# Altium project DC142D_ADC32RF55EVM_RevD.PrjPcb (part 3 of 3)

## Sheet DC142D_ADC32RF55_FMC_RevA1.SchDoc: FMC Connector
size 431 x 279 mm; Date: Not shown in title block; ApprovedBy: Not shown in title block; CheckedBy: Not shown in title block; Author: Not shown in title block; CompanyName: Not shown in title block; DrawnBy: CW; Engineer: Not shown in title block; Organization: Not shown in title block; Address1: Not shown in title block; Address2: Not shown in title block; Address3: Not shown in title block; Address4: Not shown in title block; DocumentNumber: 5; Revision: Use project parameter SCH_Rev; SheetNumber: 11; SheetTotal: 13; PageSetup: Record=PageOptions¦CenterHorizontal=True¦CenterVertical=True¦PrintScale=1.00¦XCorrection=1.00¦YCorrection=1.00¦PrintKind=0¦BorderSize=5000000¦LeftOffset=0¦BottomOffset=0¦Orientation=2¦PaperLength=1000¦PaperWidth=1000¦Scale=100¦PaperSource=15¦PrintQuality=600¦MediaType=1¦DitherType=10¦PaperKind=Letter¦PrintScaleMode=1
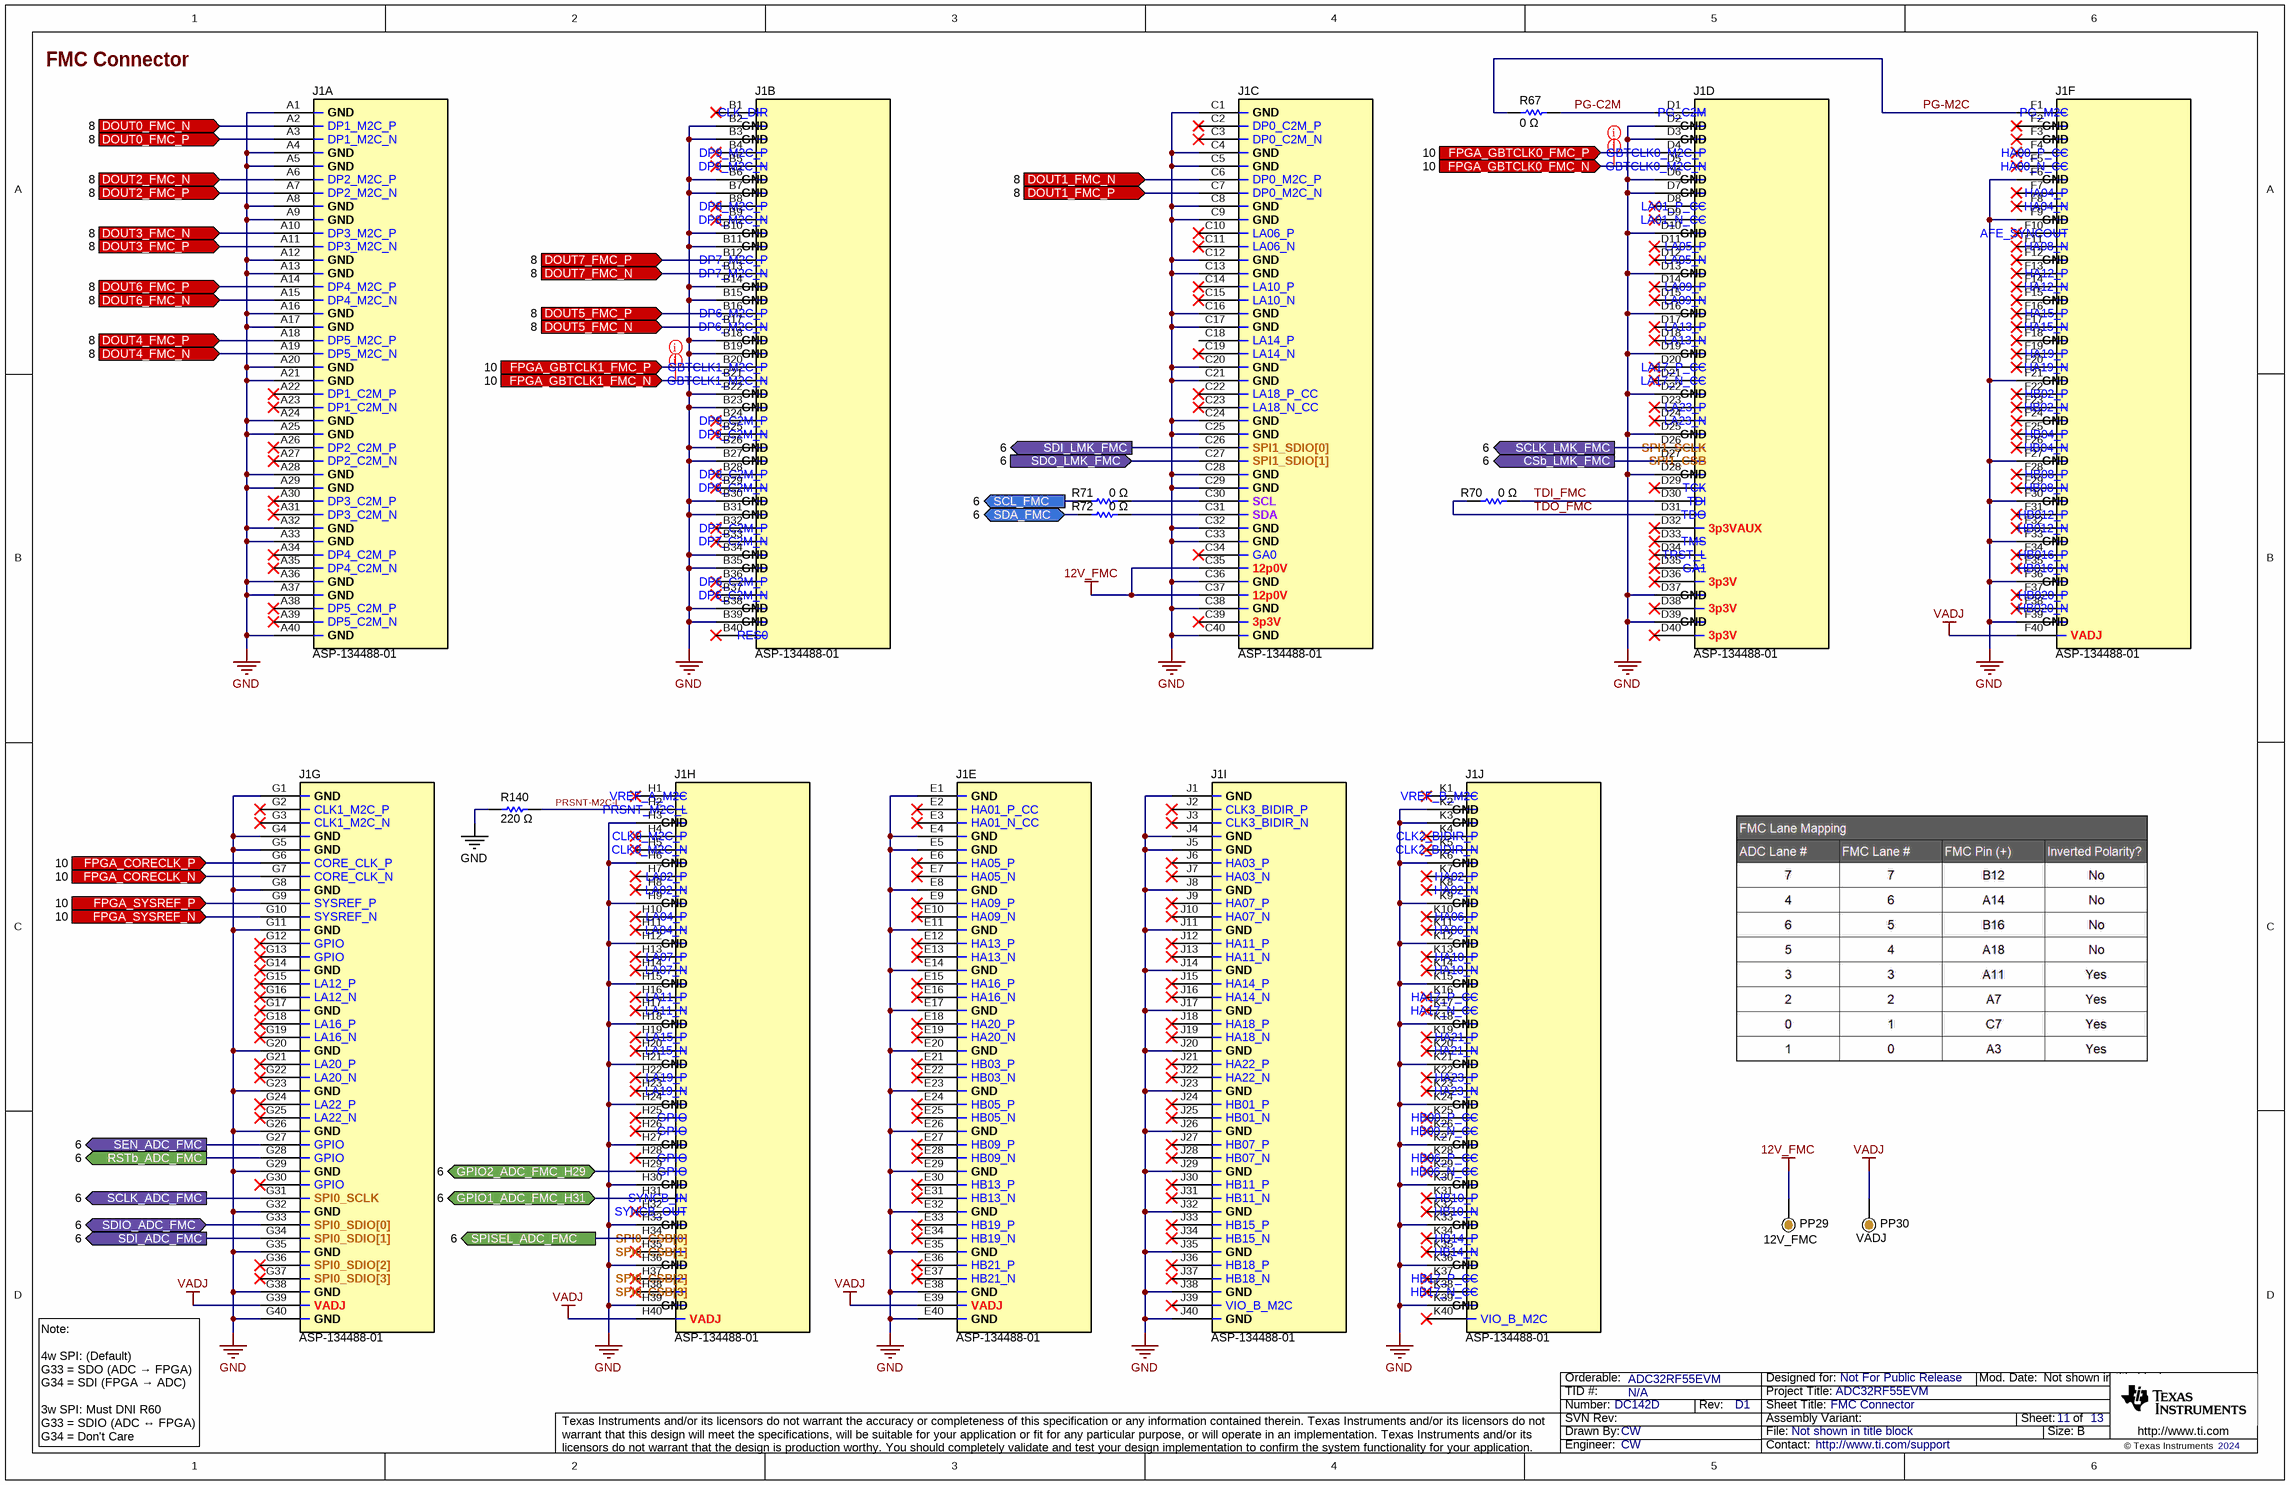
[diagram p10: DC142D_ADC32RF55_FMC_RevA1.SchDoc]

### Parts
J1  ASP-134488-01  [SAMTEC_ASP-134488-01]  (parts A,B,C,D,E,F,G,H,I,J of 10)
PP29  Text1: 12V_FMC  [ProbePoint_TH_40mil]  (hidden comment: Probe Point)  (no BOM)
PP30  Text1: VADJ  [ProbePoint_TH_40mil]  (hidden comment: Probe Point)  (no BOM)
R67  value 0 Ω  [0201]  (hidden comment: ERJ-1GN0R00C)
R70  value 0 Ω  [0201]  (hidden comment: ERJ-1GN0R00C)
R71  value 0 Ω  [0201]  (hidden comment: ERJ-1GN0R00C)
R72  value 0 Ω  [0201]  (hidden comment: ERJ-1GN0R00C)
R140  value 220 Ω  [0201]  (hidden comment: ERJ-1GNF2200C)

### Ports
CSb_LMK_FMC (out, see 6), DOUT0_FMC_N (in, see 8), DOUT0_FMC_P (in, see 8), DOUT1_FMC_N (in, see 8), DOUT1_FMC_P (in, see 8), DOUT2_FMC_N (in, see 8), DOUT2_FMC_P (in, see 8), DOUT3_FMC_N (in, see 8), DOUT3_FMC_P (in, see 8), DOUT4_FMC_N (in, see 8), DOUT4_FMC_P (in, see 8), DOUT5_FMC_N (in, see 8), DOUT5_FMC_P (in, see 8), DOUT6_FMC_N (in, see 8), DOUT6_FMC_P (in, see 8), DOUT7_FMC_N (in, see 8), DOUT7_FMC_P (in, see 8), FPGA_CORECLK_N (in, see 10), FPGA_CORECLK_P (in, see 10), FPGA_GBTCLK0_FMC_N (in, see 10), FPGA_GBTCLK0_FMC_P (in, see 10), FPGA_GBTCLK1_FMC_N (in, see 10), FPGA_GBTCLK1_FMC_P (in, see 10), FPGA_SYSREF_N (in, see 10), FPGA_SYSREF_P (in, see 10), GPIO1_ADC_FMC_H31 (bidir, see 6), GPIO2_ADC_FMC_H29 (bidir, see 6), RSTb_ADC_FMC (out, see 6), SCL_FMC (out, see 6), SCLK_ADC_FMC (out, see 6), SCLK_LMK_FMC (out, see 6), SDA_FMC (bidir, see 6), SDI_ADC_FMC (out, see 6), SDI_LMK_FMC (out, see 6), SDIO_ADC_FMC (bidir, see 6), SDO_LMK_FMC (in, see 6), SEN_ADC_FMC (out, see 6), SPISEL_ADC_FMC (out, see 6)

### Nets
12V_FMC: J1.C35 J1.C37 PP29.1
GND: J1.A1 J1.A4 J1.A5 J1.A8 J1.A9 J1.A12 J1.A13 J1.A16 J1.A17 J1.A20 J1.A21 J1.A24 J1.A25 J1.A28 J1.A29 J1.A32 J1.A33 J1.A36 J1.A37 J1.A40 J1.B2 J1.B3 J1.B6 J1.B7 J1.B10 J1.B11 J1.B14 J1.B15 J1.B18 J1.B19 J1.B22 J1.B23 J1.B26 J1.B27 J1.B30 J1.B31 J1.B34 J1.B35 J1.B38 J1.B39 J1.C1 J1.C4 J1.C5 J1.C8 J1.C9 J1.C12 J1.C13 J1.C16 J1.C17 J1.C20 J1.C21 J1.C24 J1.C25 J1.C28 J1.C29 J1.C32 J1.C33 J1.C36 J1.C38 J1.C40 J1.D2 J1.D3 J1.D6 J1.D7 J1.D10 J1.D13 J1.D16 J1.D19 J1.D22 J1.D25 J1.D28 J1.D37 J1.D39 J1.E1 J1.E4 J1.E5 J1.E8 J1.E11 J1.E14 J1.E17 J1.E20 J1.E23 J1.E26 J1.E29 J1.E32 J1.E35 J1.E38 J1.E40 J1.F6 J1.F9 J1.F21 J1.F27 J1.F30 J1.F33 J1.F36 J1.F39 J1.G1 J1.G4 J1.G5 J1.G8 J1.G11 J1.G20 J1.G23 J1.G26 J1.G29 J1.G32 J1.G35 J1.G38 J1.G40 J1.H3 J1.H6 J1.H9 J1.H12 J1.H15 J1.H18 J1.H21 J1.H24 J1.H27 J1.H30 J1.H33 J1.H36 J1.H39 J1.J1 J1.J4 J1.J5 J1.J8 J1.J11 J1.J14 J1.J17 J1.J20 J1.J23 J1.J26 J1.J29 J1.J32 J1.J35 J1.J38 J1.J40 J1.K2 J1.K3 J1.K6 J1.K9 J1.K12 J1.K15 J1.K18 J1.K21 J1.K24 J1.K27 J1.K30 J1.K33 J1.K36 J1.K39 R140.1
VADJ: J1.E39 J1.F40 J1.G39 J1.H40 PP30.1
CSb_LMK_FMC: J1.D27 ; port CSb_LMK_FMC
DOUT0_FMC_N: J1.A2 ; port DOUT0_FMC_N
DOUT0_FMC_P: J1.A3 ; port DOUT0_FMC_P
DOUT1_FMC_N: J1.C6 ; port DOUT1_FMC_N
DOUT1_FMC_P: J1.C7 ; port DOUT1_FMC_P
DOUT2_FMC_N: J1.A6 ; port DOUT2_FMC_N
DOUT2_FMC_P: J1.A7 ; port DOUT2_FMC_P
DOUT3_FMC_N: J1.A10 ; port DOUT3_FMC_N
DOUT3_FMC_P: J1.A11 ; port DOUT3_FMC_P
DOUT4_FMC_N: J1.A19 ; port DOUT4_FMC_N
DOUT4_FMC_P: J1.A18 ; port DOUT4_FMC_P
DOUT5_FMC_N: J1.B17 ; port DOUT5_FMC_N
DOUT5_FMC_P: J1.B16 ; port DOUT5_FMC_P
DOUT6_FMC_N: J1.A15 ; port DOUT6_FMC_N
DOUT6_FMC_P: J1.A14 ; port DOUT6_FMC_P
DOUT7_FMC_N: J1.B13 ; port DOUT7_FMC_N
DOUT7_FMC_P: J1.B12 ; port DOUT7_FMC_P
FPGA_CORECLK_N: J1.G7 ; port FPGA_CORECLK_N
FPGA_CORECLK_P: J1.G6 ; port FPGA_CORECLK_P
FPGA_GBTCLK0_FMC_N: J1.D5 ; port FPGA_GBTCLK0_FMC_N
FPGA_GBTCLK0_FMC_P: J1.D4 ; port FPGA_GBTCLK0_FMC_P
FPGA_GBTCLK1_FMC_N: J1.B21 ; port FPGA_GBTCLK1_FMC_N
FPGA_GBTCLK1_FMC_P: J1.B20 ; port FPGA_GBTCLK1_FMC_P
FPGA_SYSREF_N: J1.G10 ; port FPGA_SYSREF_N
FPGA_SYSREF_P: J1.G9 ; port FPGA_SYSREF_P
GPIO1_ADC_FMC_H31: J1.H31 ; port GPIO1_ADC_FMC_H31
GPIO2_ADC_FMC_H29: J1.H29 ; port GPIO2_ADC_FMC_H29
PG-C2M: J1.D1 R67.2
PG-M2C: J1.F1 R67.1
PRSNT-M2C-L: J1.H2 R140.2
RSTb_ADC_FMC: J1.G28 ; port RSTb_ADC_FMC
SCL_FMC: R71.2 ; port SCL_FMC
SCLK_ADC_FMC: J1.G31 ; port SCLK_ADC_FMC
SCLK_LMK_FMC: J1.D26 ; port SCLK_LMK_FMC
SDA_FMC: R72.2 ; port SDA_FMC
SDI_ADC_FMC: J1.G34 ; port SDI_ADC_FMC
SDI_LMK_FMC: J1.C26 ; port SDI_LMK_FMC
SDIO_ADC_FMC: J1.G33 ; port SDIO_ADC_FMC
SDO_LMK_FMC: J1.C27 ; port SDO_LMK_FMC
SEN_ADC_FMC: J1.G27 ; port SEN_ADC_FMC
SPISEL_ADC_FMC: J1.H34 ; port SPISEL_ADC_FMC
TDI_FMC: J1.D30 R70.1
TDO_FMC: J1.D31 R70.2
NetJ1_C30: J1.C30 R71.1
NetJ1_C31: J1.C31 R72.1

Not connected (* = marked no-connect by the designer): J1 A22* A23* A26* A27* A30* A31* A34* A35* A38* A39* B1* B4* B5* B8* B9* B24* B25* B28* B29* B32* B33* B36* B37* B40* C2* C3* C10* C11* C14* C15* C18 C19* C22* C23* C34* C39* D8* D9* D11* D12* D14* D15* D17* D18* D20* D21* D23* D24* D29* D32* D33* D34* D35* D36* D38* D40* E2* E3* E6* E7* E9* E10* E12* E13* E15* E16* E18* E19* E21* E22* E24* E25* E27* E28* E30* E31* E33* E34* E36* E37* F2* F3* F4* F5* F7* F8* F10* F11* F12* F13* F14* F15* F16* F17* F18* F19* F20* F22* F23* F24* F25* F26* F28* F29* F31* F32* F34* F35* F37* F38* G2* G3* G12* G13* G14* G15* G16* G17* G18* G19* G21* G22* G24* G25* G30* G36* G37* H1* H4* H5* H7* H8* H10* H11* H13* H14* H16* H17* H19* H20* H22* H23* H25* H26* H28* H32* H35* H37* H38* J2* J3* J6* J7* J9* J10* J12* J13* J15* J16* J18* J19* J21* J22* J24* J25* J27* J28* J30* J31* J33* J34* J36* J37* J39* K1* K4* K5* K7* K8* K10* K11* K13* K14* K16* K17* K19* K20* K22* K23* K25* K26* K28* K29* K31* K32* K34* K35* K37* K38* K40*

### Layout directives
net class GBT CLK: FPGA_GBTCLK0_FMC_N, FPGA_GBTCLK0_FMC_P, FPGA_GBTCLK1_FMC_N, FPGA_GBTCLK1_FMC_P

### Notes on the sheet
- Note:
  4w SPI: (Default)
  G33 = SDO (ADC → FPGA)
  G34 = SDI (FPGA → ADC)
  3w SPI: Must DNI R60
  G33 = SDIO (ADC ↔ FPGA)
  G34 = Don't Care

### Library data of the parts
J1 = ASP-134488-01: FMC, High Density Array, Male / EVM Connector 40x10; Manufacturer: Samtec; UniqueID: cmp00010; Pitch (mm): 1.27
PP29 PP30 = cmp00025: Probe Point that can be used in lue of a test point
R67 R70-R72 = RSMD020101699: RES SMD 0 OHM JUMPER 1/20W 0201; Manufacturer: Panasonic Electronic Components; CompType: Resistor SMD; Power (Watts): 0.05W, 1/20W
R140 = RSMD020100147: RES SMD 220 OHM 1% 1/20W 0201; Manufacturer: Panasonic Electronic Components; CompType: Resistor SMD; Power (Watts): 0.05W, 1/20W; Temperature Coefficient: ±200ppm/°C

## Sheet DC142D_ADC32RF55_Misc_RevA1.SchDoc: Misc Hardware
size 431 x 279 mm; Date: Not shown in title block; ApprovedBy: Not shown in title block; CheckedBy: Not shown in title block; Author: Not shown in title block; CompanyName: Not shown in title block; DrawnBy: CW; Engineer: Not shown in title block; Organization: Not shown in title block; Address1: Not shown in title block; Address2: Not shown in title block; Address3: Not shown in title block; Address4: Not shown in title block; DocumentNumber: 12; Revision: Use project parameter SCH_Rev; SheetNumber: 12; SheetTotal: 13; PageSetup: Record=PageOptions¦CenterHorizontal=True¦CenterVertical=True¦PrintScale=1.00¦XCorrection=1.00¦YCorrection=1.00¦PrintKind=0¦BorderSize=5000000¦LeftOffset=0¦BottomOffset=0¦Orientation=2¦PaperLength=1000¦PaperWidth=1000¦Scale=100¦PaperSource=15¦PrintQuality=600¦MediaType=1¦DitherType=10¦PaperKind=Letter¦PrintScaleMode=1
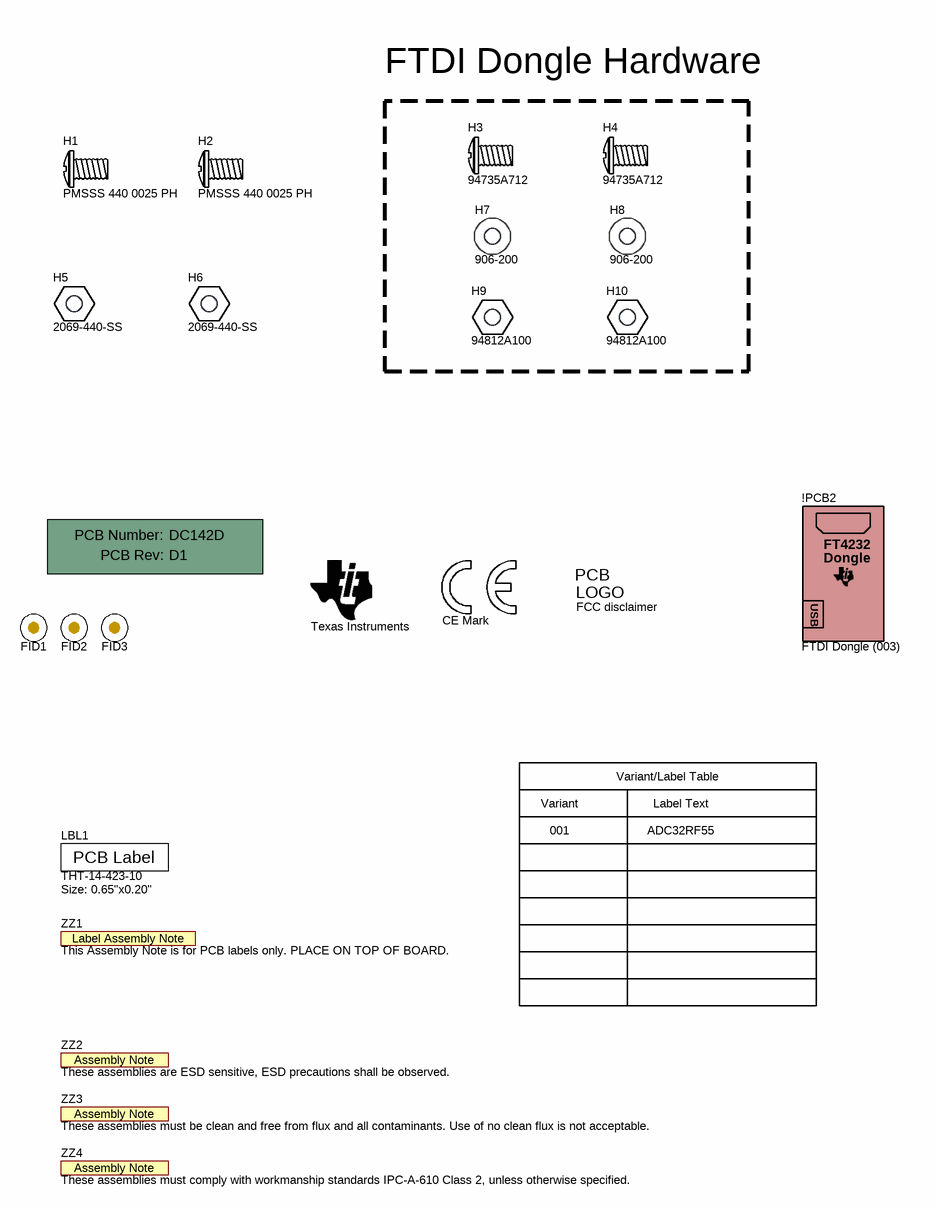
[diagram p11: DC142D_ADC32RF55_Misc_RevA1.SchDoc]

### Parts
!PCB  Printed Circuit Board  (value not drawn)  (mechanical)
!PCB2  FTDI Dongle (003)  (mechanical)
FID1  Fiducial Mark  [Fiducial10-20]  (value not drawn)  (no BOM)
FID2  Fiducial Mark  [Fiducial10-20]  (value not drawn)  (no BOM)
FID3  Fiducial Mark  [Fiducial10-20]  (value not drawn)  (no BOM)
H1  PMSSS 440 0025 PH  [4400025PH]  (mechanical)
H2  PMSSS 440 0025 PH  [4400025PH]  (mechanical)
H3  94735A712  [MCSNY 256 0025]  (mechanical)
H4  94735A712  [MCSNY 256 0025]  (mechanical)
H5  2069-440-SS  [FP-2116-440-AL_STANDOFF_HEX_1-4-MFG]
H6  2069-440-SS  [FP-2116-440-AL_STANDOFF_HEX_1-4-MFG]
H7  906-200  [Bivar_906-200]
H8  906-200  [Bivar_906-200]
H9  94812A100  [MMCNYN256]
H10  94812A100  [MMCNYN256]
LBL1  THT-14-423-10  Text1: Size: 0.65"x0.20"  [Label_650x200]
Logo1  Texas Instruments  [TI_Stacked_Overlay_Medium]  (no BOM)
LOGO2  CE Mark  [CE_Mark_5mm]  (no BOM)
Logo3  FCC disclaimer  [FCC_disclaimer]  (no BOM)
Logo4  WEEE  [WEEE_Minimum]  (value not drawn)  (no BOM)
ZZ1  This Assembly Note is for PCB labels only. PLACE ON TOP OF BOARD.  [AssemblyNoteLabel]  (no BOM)
ZZ2  These assemblies are ESD sensitive, ESD precautions shall be observed.  [AssemblyNote]  (no BOM)
ZZ3  These assemblies must be clean and free from flux and all contaminants. Use of no clean flux is not acceptable.  [AssemblyNote]  (no BOM)
ZZ4  These assemblies must comply with workmanship standards IPC-A-610 Class 2, unless otherwise specified.  [AssemblyNote]  (no BOM)

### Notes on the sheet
- FTDI Dongle Hardware
- Variant/Label Table
- Variant
- 001
- Label Text
- ADC32RF55

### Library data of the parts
!PCB = cmp00109: CompType: PCB
!PCB2 = cmp00363: FTDI Dongle RevA Variant 003; Manufacturer: Texas Instruments; CompType: Peripheral Board
FID1-FID3 = cmp00099: Fiducial; SymbolCreator: a0412235
H1 H2 = cmp00095: MACHINE SCREW PAN PHILLIPS 4-40; Manufacturer: B&F Fastener Supply
H3 H4 = cmp00392: Nylon Pan Head Screws Phillips, 2-56 Thread, 1/2" Long; Manufacturer: McMaster-Carr; CompType: Machine Screw
H5 H6 = cmp00097: Hex Standoff Threaded #4-40 Stainless Steel 1.250" (31.75mm) 1 1/4; Manufacturer: RAF Electronic Hardware; Pitch (mm): 4-40
H7 H8 = cmp00357: Round Nylon Spacer 5.08mm; Manufacturer: Bivar Inc
H9 H10 = cmp00391: Hex Nut 3/16" Nylon 2-56; Manufacturer: McMaster-Carr; CompType: Hex Nut
LBL1 = cmp00106: Thermal Transfer Printable Labels, 0.650" W x 0.200" H - 10,000 per roll; Manufacturer: Brady; CompType: Label
Logo1 = cmp00104: Texas Instrument Corporate Signature; PartNumber: TI Bug; CompType: Logo
LOGO2 = cmp00103: CE_Mark; CompType: Logo
Logo3 = CMP-0074847-1: FCC_disclaimer; Library Reference: Logo
Logo4 = cmp00101: CompType: Logo
ZZ1 = cmp00107: This Assembly Note is for PCB labels only; SymbolCreator: a0412235
ZZ2 = CMP-0077236-1
ZZ3 = CMP-0077237-1
ZZ4 = CMP-0077238-1

## Sheet DC142D_ADC32RF55_Revision History.SchDoc: Rev History & Variants
size 431 x 279 mm; Date: Not shown in title block; ApprovedBy: Not shown in title block; CheckedBy: Not shown in title block; Author: Not shown in title block; CompanyName: Not shown in title block; DrawnBy: CW; Engineer: Not shown in title block; Organization: Not shown in title block; Address1: Not shown in title block; Address2: Not shown in title block; Address3: Not shown in title block; Address4: Not shown in title block; DocumentNumber: 13; Revision: Use project parameter SCH_Rev; SheetNumber: 13; SheetTotal: 13; PageSetup: Record=PageOptions¦CenterHorizontal=True¦CenterVertical=True¦PrintScale=1.00¦XCorrection=1.00¦YCorrection=1.00¦PrintKind=0¦BorderSize=5000000¦LeftOffset=0¦BottomOffset=0¦Orientation=2¦PaperLength=1000¦PaperWidth=1000¦Scale=100¦PaperSource=15¦PrintQuality=600¦MediaType=1¦DitherType=10¦PaperKind=Letter¦PrintScaleMode=1
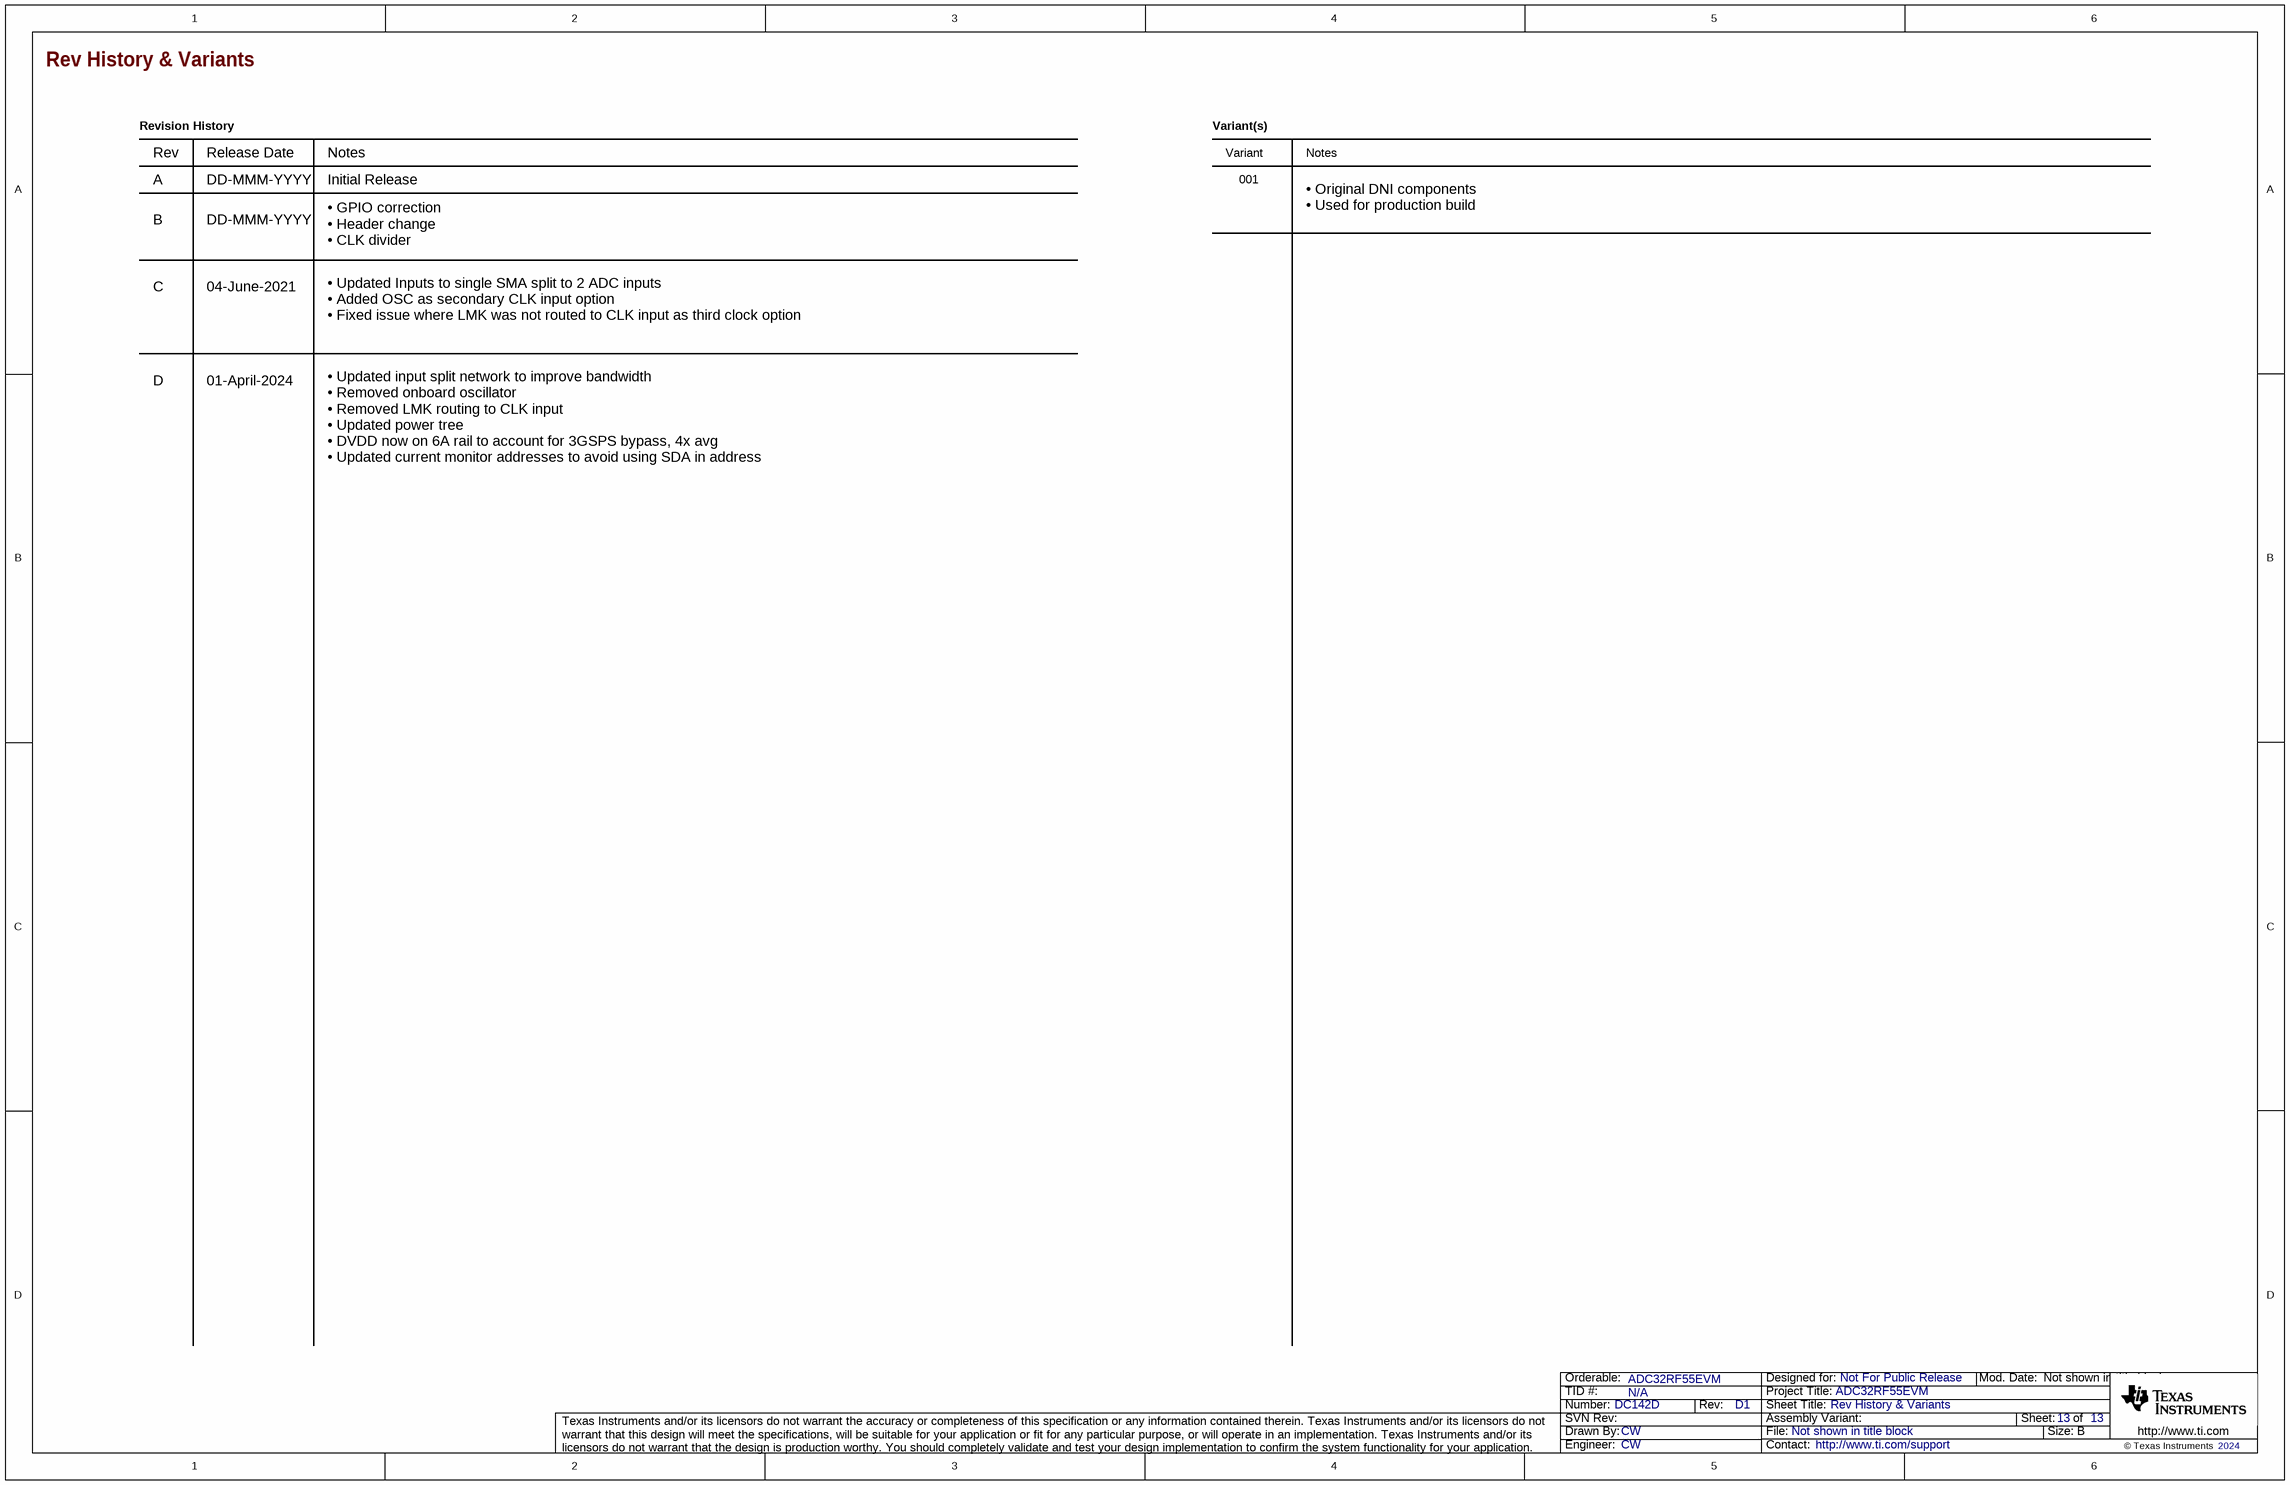
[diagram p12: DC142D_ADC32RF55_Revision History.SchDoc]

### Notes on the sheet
- Revision History
- Rev
- Release Date
- Notes
- Variant(s)
- Variant
- A
- B
- DD-MMM-YYYY
- Initial Release
- 001
- C
- 04-June-2021
- • GPIO correction
  • Header change
  • CLK divider
- • Original DNI components
  • Used for production build
- • Updated Inputs to single SMA split to 2 ADC inputs
  • Added OSC as secondary CLK input option
  • Fixed issue where LMK was not routed to CLK input as third clock option
- D
- 01-April-2024
- • Updated input split network to improve bandwidth
  • Removed onboard oscillator
  • Removed LMK routing to CLK input
  • Updated power tree
  • DVDD now on 6A rail to account for 3GSPS bypass, 4x avg
  • Updated current monitor addresses to avoid using SDA in address

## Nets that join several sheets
3p3V_Utility: DC142D_ADC32RF55_Power1_RevA1 (5 pins), DC142D_ADC32RF55_Power2_RevA1 (9 pins), DC142D_ADC32RF55_Power3_RevA1 (9 pins), DC142D_ADC32RF55_USB_RevA1 (19 pins), DC142D_ADC32RF55_MUX_RevA1 (12 pins), DC142D_ADC32RF55_ADC_Power_RevA1 (C132.2 U29.B1 U29.C1), DC142D_ADC32RF55_LMK_RevA1 (26 pins)
12V: DC142D_ADC32RF55_Power1_RevA1 (9 pins), DC142D_ADC32RF55_Power2_RevA1 (C19.2 C20.2 R11.1 U6.18), DC142D_ADC32RF55_Power3_RevA1 (11 pins)
12V_FMC: DC142D_ADC32RF55_Power1_RevA1 (SW1.1), DC142D_ADC32RF55_FMC_RevA1 (J1.C35 J1.C37 PP29.1)
AVDD12: DC142D_ADC32RF55_Power2_RevA1 (FC4.3 PP8.1), DC142D_ADC32RF55_ADC_Power_RevA1 (11 pins)
AVDD18: DC142D_ADC32RF55_Power3_RevA1 (FC6.3 PP12.1), DC142D_ADC32RF55_ADC_Dig_RevA1 (5 pins), DC142D_ADC32RF55_ADC_Power_RevA1 (11 pins)
CLKVDD: DC142D_ADC32RF55_Power2_RevA1 (FC3.3 PP6.1), DC142D_ADC32RF55_ADC_Power_RevA1 (C120.2 C121.2 U1.25)
DVDD: DC142D_ADC32RF55_Power3_RevA1 (6 pins), DC142D_ADC32RF55_ADC_Power_RevA1 (18 pins)
GND: DC142D_ADC32RF55_Power1_RevA1 (39 pins), DC142D_ADC32RF55_Power2_RevA1 (53 pins), DC142D_ADC32RF55_Power3_RevA1 (57 pins), DC142D_ADC32RF55_USB_RevA1 (40 pins), DC142D_ADC32RF55_MUX_RevA1 (25 pins), DC142D_ADC32RF55_ADC_Input_RevA1 (16 pins), DC142D_ADC32RF55_ADC_Dig_RevA1 (12 pins), DC142D_ADC32RF55_ADC_Power_RevA1 (36 pins), DC142D_ADC32RF55_LMK_RevA1 (25 pins), DC142D_ADC32RF55_FMC_RevA1 (152 pins)
VADJ: DC142D_ADC32RF55_MUX_RevA1 (7 pins), DC142D_ADC32RF55_FMC_RevA1 (5 pins)
VDDL18: DC142D_ADC32RF55_Power3_RevA1 (C65.2 PP13.1 U15.1), DC142D_ADC32RF55_USB_RevA1 (U21.13 U22.2 U22.5 U23.13), DC142D_ADC32RF55_MUX_RevA1 (R56.1 R57.1)
ADC_SYSREF_N: DC142D_ADC32RF55_ADC_Dig_RevA1 (R74.2 U1.28), DC142D_ADC32RF55_LMK_RevA1 (R146.1 R150.1)
ADC_SYSREF_P: DC142D_ADC32RF55_ADC_Dig_RevA1 (R74.1 U1.27), DC142D_ADC32RF55_LMK_RevA1 (R147.1 R149.1)
CLK_LMK: DC142D_ADC32RF55_ADC_Dig_RevA1 (R135.2), DC142D_ADC32RF55_LMK_RevA1 (C105.1)
CSb_LMK: DC142D_ADC32RF55_MUX_RevA1 (R46.2), DC142D_ADC32RF55_LMK_RevA1 (U2.18)
CSb_LMK_FMC: DC142D_ADC32RF55_MUX_RevA1 (R47.2 U17.2), DC142D_ADC32RF55_FMC_RevA1 (J1.D27)
CSb_LMK_USB: DC142D_ADC32RF55_USB_RevA1 (J3.29), DC142D_ADC32RF55_MUX_RevA1 (R40.2 U16.3)
DOUT0_FMC_N: DC142D_ADC32RF55_ADC_Dig_RevA1 (C85.2), DC142D_ADC32RF55_FMC_RevA1 (J1.A2)
DOUT0_FMC_P: DC142D_ADC32RF55_ADC_Dig_RevA1 (C84.2), DC142D_ADC32RF55_FMC_RevA1 (J1.A3)
DOUT1_FMC_N: DC142D_ADC32RF55_ADC_Dig_RevA1 (C87.2), DC142D_ADC32RF55_FMC_RevA1 (J1.C6)
DOUT1_FMC_P: DC142D_ADC32RF55_ADC_Dig_RevA1 (C86.2), DC142D_ADC32RF55_FMC_RevA1 (J1.C7)
DOUT2_FMC_N: DC142D_ADC32RF55_ADC_Dig_RevA1 (C89.2), DC142D_ADC32RF55_FMC_RevA1 (J1.A6)
DOUT2_FMC_P: DC142D_ADC32RF55_ADC_Dig_RevA1 (C88.2), DC142D_ADC32RF55_FMC_RevA1 (J1.A7)
DOUT3_FMC_N: DC142D_ADC32RF55_ADC_Dig_RevA1 (C93.2), DC142D_ADC32RF55_FMC_RevA1 (J1.A10)
DOUT3_FMC_P: DC142D_ADC32RF55_ADC_Dig_RevA1 (C90.2), DC142D_ADC32RF55_FMC_RevA1 (J1.A11)
DOUT4_FMC_N: DC142D_ADC32RF55_ADC_Dig_RevA1 (C95.2), DC142D_ADC32RF55_FMC_RevA1 (J1.A19)
DOUT4_FMC_P: DC142D_ADC32RF55_ADC_Dig_RevA1 (C94.2), DC142D_ADC32RF55_FMC_RevA1 (J1.A18)
DOUT5_FMC_N: DC142D_ADC32RF55_ADC_Dig_RevA1 (C97.2), DC142D_ADC32RF55_FMC_RevA1 (J1.B17)
DOUT5_FMC_P: DC142D_ADC32RF55_ADC_Dig_RevA1 (C96.2), DC142D_ADC32RF55_FMC_RevA1 (J1.B16)
DOUT6_FMC_N: DC142D_ADC32RF55_ADC_Dig_RevA1 (C100.2), DC142D_ADC32RF55_FMC_RevA1 (J1.A15)
DOUT6_FMC_P: DC142D_ADC32RF55_ADC_Dig_RevA1 (C98.2), DC142D_ADC32RF55_FMC_RevA1 (J1.A14)
DOUT7_FMC_N: DC142D_ADC32RF55_ADC_Dig_RevA1 (C104.2), DC142D_ADC32RF55_FMC_RevA1 (J1.B13)
DOUT7_FMC_P: DC142D_ADC32RF55_ADC_Dig_RevA1 (C102.2), DC142D_ADC32RF55_FMC_RevA1 (J1.B12)
FPGA_CORECLK_N: DC142D_ADC32RF55_LMK_RevA1 (C138.2), DC142D_ADC32RF55_FMC_RevA1 (J1.G7)
FPGA_CORECLK_P: DC142D_ADC32RF55_LMK_RevA1 (C137.2), DC142D_ADC32RF55_FMC_RevA1 (J1.G6)
FPGA_GBTCLK0_FMC_N: DC142D_ADC32RF55_LMK_RevA1 (C136.2), DC142D_ADC32RF55_FMC_RevA1 (J1.D5)
FPGA_GBTCLK0_FMC_P: DC142D_ADC32RF55_LMK_RevA1 (C135.2), DC142D_ADC32RF55_FMC_RevA1 (J1.D4)
FPGA_GBTCLK1_FMC_N: DC142D_ADC32RF55_LMK_RevA1 (C134.2), DC142D_ADC32RF55_FMC_RevA1 (J1.B21)
FPGA_GBTCLK1_FMC_P: DC142D_ADC32RF55_LMK_RevA1 (C133.2), DC142D_ADC32RF55_FMC_RevA1 (J1.B20)
FPGA_SYSREF_N: DC142D_ADC32RF55_LMK_RevA1 (R157.1 R161.1), DC142D_ADC32RF55_FMC_RevA1 (J1.G10)
FPGA_SYSREF_P: DC142D_ADC32RF55_LMK_RevA1 (R158.1 R160.1), DC142D_ADC32RF55_FMC_RevA1 (J1.G9)
GPIO1_ADC: DC142D_ADC32RF55_MUX_RevA1 (PP23.1 U32.2), DC142D_ADC32RF55_ADC_Dig_RevA1 (U1.39)
GPIO1_ADC_FMC_H31: DC142D_ADC32RF55_MUX_RevA1 (U32.1), DC142D_ADC32RF55_FMC_RevA1 (J1.H31)
GPIO1_ADC_USB: DC142D_ADC32RF55_USB_RevA1 (U23.12), DC142D_ADC32RF55_MUX_RevA1 (U32.16)
GPIO2_ADC: DC142D_ADC32RF55_MUX_RevA1 (PP24.1 U32.5), DC142D_ADC32RF55_ADC_Dig_RevA1 (U1.38)
GPIO2_ADC_FMC_H29: DC142D_ADC32RF55_MUX_RevA1 (U32.4), DC142D_ADC32RF55_FMC_RevA1 (J1.H29)
GPIO2_ADC_USB: DC142D_ADC32RF55_USB_RevA1 (U23.11), DC142D_ADC32RF55_MUX_RevA1 (U32.3)
INA1_ADC_N: DC142D_ADC32RF55_ADC_Input_RevA1 (C68.2 R104.2), DC142D_ADC32RF55_ADC_Dig_RevA1 (U1.15)
INA1_ADC_P: DC142D_ADC32RF55_ADC_Input_RevA1 (C74.2 R104.1), DC142D_ADC32RF55_ADC_Dig_RevA1 (U1.14)
INA2_ADC_N: DC142D_ADC32RF55_ADC_Input_RevA1 (C78.2 R111.1), DC142D_ADC32RF55_ADC_Dig_RevA1 (U1.19)
INA2_ADC_P: DC142D_ADC32RF55_ADC_Input_RevA1 (C75.2 R111.2), DC142D_ADC32RF55_ADC_Dig_RevA1 (U1.18)
INB1_ADC_N: DC142D_ADC32RF55_ADC_Input_RevA1 (C155.2 R126.2), DC142D_ADC32RF55_ADC_Dig_RevA1 (U1.34)
INB1_ADC_P: DC142D_ADC32RF55_ADC_Input_RevA1 (C158.2 R126.1), DC142D_ADC32RF55_ADC_Dig_RevA1 (U1.35)
INB2_ADC_N: DC142D_ADC32RF55_ADC_Input_RevA1 (C79.2 R119.2), DC142D_ADC32RF55_ADC_Dig_RevA1 (U1.30)
INB2_ADC_P: DC142D_ADC32RF55_ADC_Input_RevA1 (C154.2 R119.1), DC142D_ADC32RF55_ADC_Dig_RevA1 (U1.31)
PG-AVDD12: DC142D_ADC32RF55_Power2_RevA1 (R23.1 U9.8), DC142D_ADC32RF55_Power3_RevA1 (R31.2 U13.24)
PG-DVDD12: DC142D_ADC32RF55_Power2_RevA1 (R11.2 U6.24), DC142D_ADC32RF55_Power3_RevA1 (R155.1 U31.3)
RSTb_ADC: DC142D_ADC32RF55_MUX_RevA1 (R62.2), DC142D_ADC32RF55_ADC_Dig_RevA1 (R24.2 U27.1)
RSTb_ADC_FMC: DC142D_ADC32RF55_MUX_RevA1 (U18.11), DC142D_ADC32RF55_FMC_RevA1 (J1.G28)
RSTb_ADC_USB: DC142D_ADC32RF55_USB_RevA1 (U23.9), DC142D_ADC32RF55_MUX_RevA1 (U18.12)
SCL_FMC: DC142D_ADC32RF55_MUX_RevA1 (U20.2), DC142D_ADC32RF55_FMC_RevA1 (R71.2)
SCL_I2C: DC142D_ADC32RF55_Power1_RevA1 (U30.A1 U30.B3), DC142D_ADC32RF55_Power2_RevA1 (U5.A1 U8.A1 U33.A2), DC142D_ADC32RF55_Power3_RevA1 (U10.A1 U12.A1), DC142D_ADC32RF55_USB_RevA1 (U25.6), DC142D_ADC32RF55_MUX_RevA1 (PP26.1 R73.2), DC142D_ADC32RF55_ADC_Power_RevA1 (U29.A2)
SCL_USB: DC142D_ADC32RF55_USB_RevA1 (R90.1 R91.2), DC142D_ADC32RF55_MUX_RevA1 (U20.1)
SCLK_ADC: DC142D_ADC32RF55_MUX_RevA1 (R58.2), DC142D_ADC32RF55_ADC_Dig_RevA1 (U1.55)
SCLK_ADC_FMC: DC142D_ADC32RF55_MUX_RevA1 (U18.1), DC142D_ADC32RF55_FMC_RevA1 (J1.G31)
SCLK_ADC_USB: DC142D_ADC32RF55_USB_RevA1 (U21.12), DC142D_ADC32RF55_MUX_RevA1 (U18.16)
SCLK_LMK: DC142D_ADC32RF55_MUX_RevA1 (R45.2), DC142D_ADC32RF55_LMK_RevA1 (U2.19)
SCLK_LMK_FMC: DC142D_ADC32RF55_MUX_RevA1 (R53.1 U17.1), DC142D_ADC32RF55_FMC_RevA1 (J1.D26)
SCLK_LMK_USB: DC142D_ADC32RF55_USB_RevA1 (J3.33), DC142D_ADC32RF55_MUX_RevA1 (R42.1 U16.16)
SDA_FMC: DC142D_ADC32RF55_MUX_RevA1 (U20.6), DC142D_ADC32RF55_FMC_RevA1 (R72.2)
SDA_I2C: DC142D_ADC32RF55_Power1_RevA1 (U30.A2), DC142D_ADC32RF55_Power2_RevA1 (U5.A2 U8.A2 U33.A1), DC142D_ADC32RF55_Power3_RevA1 (U10.A2 U12.A2), DC142D_ADC32RF55_USB_RevA1 (U25.5), DC142D_ADC32RF55_MUX_RevA1 (PP27.1 R77.2), DC142D_ADC32RF55_ADC_Power_RevA1 (U29.A1)
SDA_USB: DC142D_ADC32RF55_USB_RevA1 (R55.2 R80.2), DC142D_ADC32RF55_MUX_RevA1 (U20.7)
SDI_ADC_FMC: DC142D_ADC32RF55_MUX_RevA1 (R75.1 U19.1), DC142D_ADC32RF55_FMC_RevA1 (J1.G34)
SDI_LMK: DC142D_ADC32RF55_MUX_RevA1 (R48.2), DC142D_ADC32RF55_LMK_RevA1 (U2.20)
SDI_LMK_FMC: DC142D_ADC32RF55_MUX_RevA1 (R54.1 U17.3), DC142D_ADC32RF55_FMC_RevA1 (J1.C26)
SDI_LMK_USB: DC142D_ADC32RF55_USB_RevA1 (J3.35), DC142D_ADC32RF55_MUX_RevA1 (R43.1 U16.9)
SDIO_ADC: DC142D_ADC32RF55_MUX_RevA1 (R59.2), DC142D_ADC32RF55_ADC_Dig_RevA1 (U1.56)
SDIO_ADC_FMC: DC142D_ADC32RF55_MUX_RevA1 (R60.2 U18.4), DC142D_ADC32RF55_FMC_RevA1 (J1.G33)
SDIO_ADC_USB: DC142D_ADC32RF55_USB_RevA1 (R88.2 U21.11), DC142D_ADC32RF55_MUX_RevA1 (U18.3)
SDO_LMK: DC142D_ADC32RF55_MUX_RevA1 (R49.2), DC142D_ADC32RF55_LMK_RevA1 (U2.5)
SDO_LMK_FMC: DC142D_ADC32RF55_MUX_RevA1 (U17.4), DC142D_ADC32RF55_FMC_RevA1 (J1.C27)
SDO_LMK_USB: DC142D_ADC32RF55_USB_RevA1 (J3.27), DC142D_ADC32RF55_MUX_RevA1 (R44.1 U16.12)
SEN_ADC: DC142D_ADC32RF55_MUX_RevA1 (R61.2), DC142D_ADC32RF55_ADC_Dig_RevA1 (U1.57)
SEN_ADC_FMC: DC142D_ADC32RF55_MUX_RevA1 (U18.8), DC142D_ADC32RF55_FMC_RevA1 (J1.G27)
SEN_ADC_USB: DC142D_ADC32RF55_USB_RevA1 (U21.10), DC142D_ADC32RF55_MUX_RevA1 (U18.9)
SPISEL_ADC: DC142D_ADC32RF55_MUX_RevA1 (PP25.1 U32.7), DC142D_ADC32RF55_ADC_Dig_RevA1 (U1.10)
SPISEL_ADC_FMC: DC142D_ADC32RF55_MUX_RevA1 (U32.8), DC142D_ADC32RF55_FMC_RevA1 (J1.H34)
SPISEL_ADC_USB: DC142D_ADC32RF55_USB_RevA1 (U23.10), DC142D_ADC32RF55_MUX_RevA1 (U32.9)

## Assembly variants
-001: not fitted C107 C108 C162 C168 F1 H3 H4 H7 H8 H9 H10 R4 R8 R11 R28 R31 R65 R65 R68 R69 R70 R70 R74 R74 R75 R75 R76 R76 R78 R81 R92 R93 R99 R105 R106 R119 R120 R133 R133 R143 R143 R144 R144 R146 R147 R147 R148 R148 R157 R158 R159 R165 R180 R185 U27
